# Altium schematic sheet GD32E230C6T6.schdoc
size 127 x 101 mm
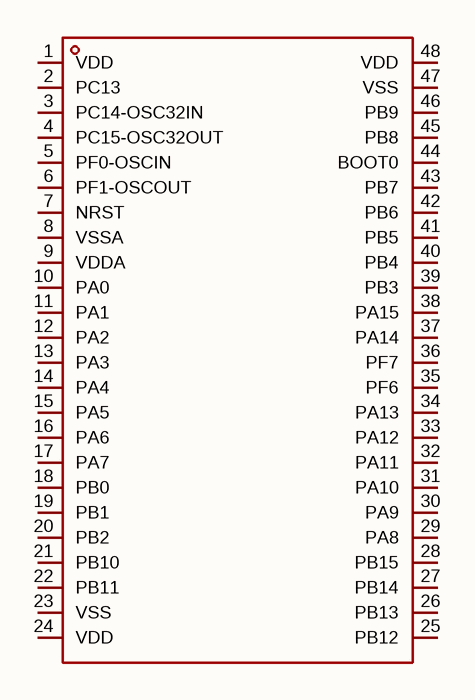
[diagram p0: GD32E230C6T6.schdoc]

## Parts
U?  gd32e230c6t6  [LQFP-48_L7.0-W7.0-P0.50-LS9.0-BL]  (value not drawn)

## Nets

Not connected (* = marked no-connect by the designer): U? 1(VDD) 2(PC13) 3(PC14-OSC32IN) 4(PC15-OSC32OUT) 5(PF0-OSCIN) 6(PF1-OSCOUT) 7(NRST) 8(VSSA) 9(VDDA) 10(PA0) 11(PA1) 12(PA2) 13(PA3) 14(PA4) 15(PA5) 16(PA6) 17(PA7) 18(PB0) 19(PB1) 20(PB2) 21(PB10) 22(PB11) 23(VSS) 24(VDD) 25(PB12) 26(PB13) 27(PB14) 28(PB15) 29(PA8) 30(PA9) 31(PA10) 32(PA11) 33(PA12) 34(PA13) 35(PF6) 36(PF7) 37(PA14) 38(PA15) 39(PB3) 40(PB4) 41(PB5) 42(PB6) 43(PB7) 44(BOOT0) 45(PB8) 46(PB9) 47(VSS) 48(VDD)

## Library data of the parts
U? = gd32e230c6t6: CPU内核:ARM Cortex-M系列;; Manufacturer: GigaDevice(兆易创新); AddInBom: yes; ModelId: 093be70396ff421eb2cdb946d5311efc; ModelName: LQFP-48_L7.0-W7.0-H1.4-LS9.0-P0.50; ModelTransform: 354.331,354.331,0,0,0,0,0,0,0; Program Storage Size: 32KB; Program Memory Type: FLASH; ADC (Bit): 12bit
